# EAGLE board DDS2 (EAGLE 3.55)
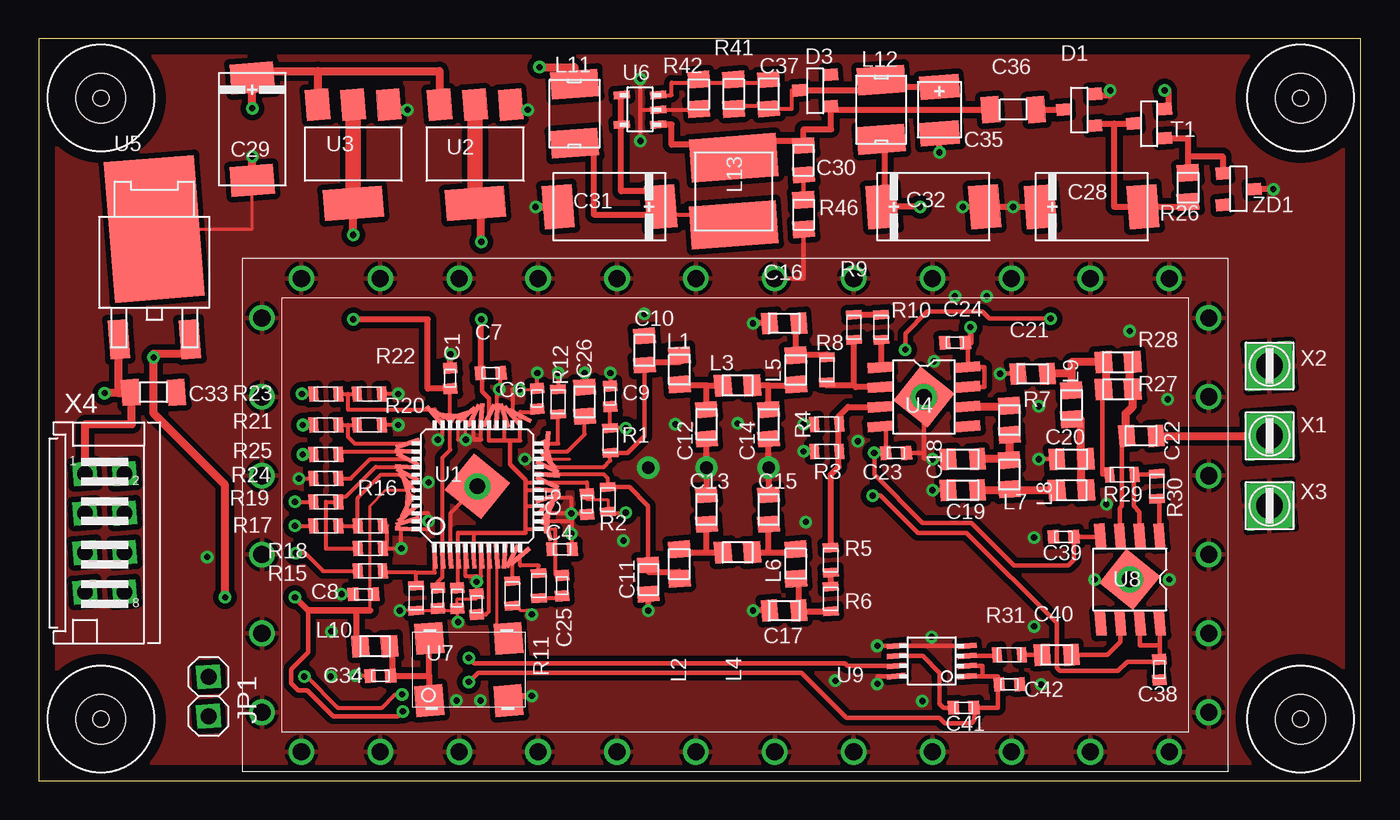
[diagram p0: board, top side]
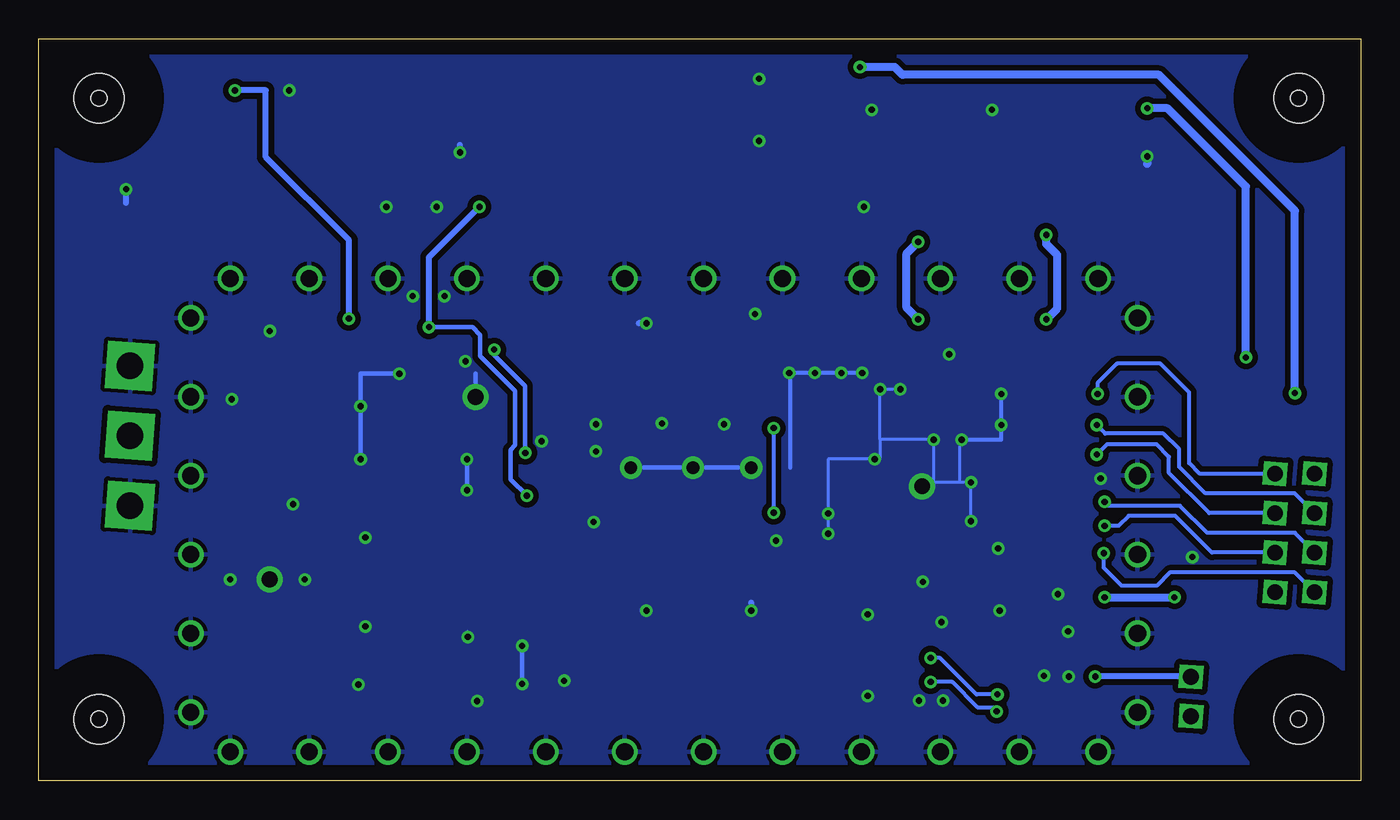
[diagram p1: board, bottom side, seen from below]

Size 85.11 x 47.79 mm. Coordinates in mm from the lower left corner, seen from the top.
Outline: 0,0 85.11,0 85.11,47.79 0,47.79 0,0
Copper layers used: Top, Bottom

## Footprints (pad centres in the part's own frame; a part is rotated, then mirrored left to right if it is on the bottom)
T-0603 = smd 0.7 x 0.9 rotated 4.4:  0.66,0 | smd 0.7 x 0.9 rotated 4.3:  -0.66,0
T-0805 = smd 1.016 x 1.397 rotated 4.4:  0.94,0 | smd 1.016 x 1.397 rotated 4.3:  -0.94,0
J_D = smd 1.93 x 2.794 rotated 4.3:  -3.302,0 | smd 1.93 x 2.794 rotated 4.4:  3.302,0
T-1206 = smd 1.143 x 1.702 rotated 4.4:  1.473,0 | smd 1.143 x 1.702 rotated 4.3:  -1.473,0
J_B = smd 1.524 x 2.54 rotated 4.3:  -1.46,0 | smd 1.524 x 2.54 rotated 4.4:  1.524,0
T-23 = smd 0.787 x 0.889 rotated 4.4:  1.016,1.016 | smd 0.787 x 0.889 rotated 4.3:  -1.016,1.016 | smd 0.787 x 0.889 rotated 4.5:  0,-1.016
02 = drill 1.016 pad 1.524 square:  -1.27,0;  1.27,0
D-0805 = smd 1.092 x 1.397 rotated 4.4:  0.94,0 | smd 1.092 x 1.397 rotated 4.3:  -0.94,0
LE-SMD = smd 1.778 x 3.048 rotated 4.3:  -1.905,0 | smd 1.778 x 3.048 rotated 4.4:  1.905,0
-TPC-M = smd 5.588 x 2.794 rotated 4.3:  0,2.159 | smd 5.588 x 2.794 rotated 4.4:  0,-2.159
D-0603 = smd 0.6 x 1 rotated 4.3:  -0.8,0 | smd 0.6 x 1 rotated 4.4:  0.8,0
31X62 = drill 1.1 pad 1.6 round:  2.54,30.48;  -2.54,30.48;  -12.7,30.48;  12.7,30.48;  -15.24,2.54;  -15.24,7.62;  -15.24,27.94;  15.24,27.94;  15.24,7.62;  15.24,2.54;  15.24,-2.54;  15.24,-27.94;  12.7,-30.48;  2.54,-30.48;  -2.54,-30.48;  -12.7,-30.48;  -15.24,-27.94;  -15.24,-2.54;  15.24,12.7;  -15.24,12.7;  -15.24,-7.62;  15.24,-7.62;  -15.24,22.86;  -15.24,17.78;  15.24,22.86;  15.24,17.78;  -15.24,-12.7;  -15.24,-17.78;  15.24,-12.7;  15.24,-17.78;  15.24,-22.86;  -15.24,-22.86;  -7.62,30.48;  7.62,30.48;  -7.62,-30.48;  7.62,-30.48
T-23' = smd 0.787 x 0.889 rotated 4.3:  0.94,1.016 | smd 0.787 x 0.889 rotated 4.4:  -0.94,1.016 | smd 0.787 x 0.889 rotated 4.5:  0,-1.016
C_SQ48 = smd 1.6 x 0.28 rotated 4.3:  -4.5,2.75;  -4.5,-1.75 | smd 1.6 x 0.28 rotated 4.4:  -4.5,2.25 | smd 1.6 x 0.28 rotated 4.5:  -4.5,1.75;  4.55,-0.25 | smd 1.6 x 0.28 rotated 4.6:  -4.5,1.25 | smd 1.6 x 0.28 rotated 4.7:  -4.5,0.75;  -4.5,0.25 | smd 1.6 x 0.28 rotated 4.8:  -4.5,-0.25 | smd 1.6 x 0.28 rotated 4.9:  -4.5,-0.75 | smd 1.6 x 0.28 rotated 5:  -4.5,-1.25 | smd 1.6 x 0.28 rotated 26.8:  -4.5,-2.25 | smd 1.6 x 0.28 rotated 49.3:  -4.5,-2.75 | smd 0.28 x 1.6 rotated 71.8:  -2.75,-4.5 | smd 0.28 x 1.6 rotated 94.3:  -2.25,-4.5 | smd 0.28 x 1.6 rotated 116.8:  -1.75,-4.5 | smd 0.28 x 1.6 rotated 139.3:  -1.25,-4.5 | smd 0.28 x 1.6 rotated 161.8:  -0.75,-4.5 | smd 0.28 x 1.6 rotated 184.3:  -0.25,-4.5 | smd 0.28 x 1.6 rotated 206.8:  0.25,-4.5 | smd 0.28 x 1.6 rotated 4.4:  0.75,-4.5 | smd 0.28 x 1.6 rotated 26.9:  1.25,-4.5 | smd 0.28 x 1.6 rotated 49.4:  1.75,-4.5 | smd 0.28 x 1.6 rotated 71.9:  2.25,-4.5 | smd 0.28 x 1.6 rotated 94.4:  2.75,-4.5 | smd 1.6 x 0.28 rotated 116.9:  4.55,-2.75 | smd 1.6 x 0.28 rotated 139.4:  4.55,-2.25 | smd 1.6 x 0.28 rotated 161.9:  4.55,-1.75 | smd 1.6 x 0.28 rotated 184.4:  4.55,-1.25 | smd 1.6 x 0.28 rotated 206.9:  4.55,-0.75 | smd 1.6 x 0.28 rotated 27:  4.55,0.25 | smd 1.6 x 0.28 rotated 49.5:  4.55,0.75 | smd 1.6 x 0.28 rotated 72:  4.55,1.25 | smd 1.6 x 0.28 rotated 94.5:  4.55,1.75 | smd 1.6 x 0.28 rotated 117:  4.55,2.25 | smd 1.6 x 0.28 rotated 139.5:  4.55,2.75 | smd 0.28 x 1.6 rotated 162:  2.75,4.5 | smd 0.28 x 1.6 rotated 184.5:  2.25,4.5 | smd 0.28 x 1.6 rotated 207:  1.75,4.5 | smd 0.28 x 1.6 rotated 4.6:  1.25,4.5 | smd 0.28 x 1.6 rotated 27.1:  0.75,4.5 | smd 0.28 x 1.6 rotated 49.6:  0.25,4.5 | smd 0.28 x 1.6 rotated 72.1:  -0.25,4.5 | smd 0.28 x 1.6 rotated 94.6:  -0.75,4.5 | smd 0.28 x 1.6 rotated 117.1:  -1.25,4.5 | smd 0.28 x 1.6 rotated 139.6:  -1.75,4.5 | smd 0.28 x 1.6 rotated 162.1:  -2.25,4.5 | smd 0.28 x 1.6 rotated 184.6:  -2.75,4.5 | smd 3 x 3 rotated 321.2:  0,0
T-223 = smd 1.499 x 2.007 rotated 4.3:  -2.286,-3.175 | smd 1.499 x 2.007 rotated 4.4:  0,-3.175 | smd 1.499 x 2.007 rotated 4.5:  2.286,-3.175 | smd 3.81 x 2.007 rotated 4.6:  0,3.175
-8EXP = smd 0.66 x 1.6 rotated 4.3:  -1.905,-2.819 | smd 0.66 x 1.6 rotated 4.9:  -1.93,2.819 | smd 0.66 x 1.6 rotated 4.4:  -0.635,-2.819 | smd 0.66 x 1.6 rotated 4.5:  0.635,-2.819 | smd 0.66 x 1.6 rotated 4.8:  -0.66,2.819 | smd 0.66 x 1.6 rotated 4.7:  0.61,2.819;  1.88,2.819 | smd 0.66 x 1.6 rotated 4.6:  1.905,-2.819 | smd 2.794 x 2.794 rotated 321.2:  0,0
AK = smd 1.27 x 2.54 rotated 4.3:  -2.286,-2.032 | smd 1.27 x 2.54 rotated 4.4:  2.286,-2.032 | smd 5.8 x 9.1 rotated 4.5:  0,5.08
T23-5 = smd 1.016 x 0.508 rotated 4.3:  -1.143,0.953 | smd 1.016 x 0.508 rotated 4.4:  -1.143,0 | smd 1.016 x 0.508 rotated 4.5:  -1.143,-0.953 | smd 1.016 x 0.508 rotated 4.6:  1.206,-0.953 | smd 1.016 x 0.508 rotated 4.7:  1.206,0.953
710 = smd 1.8 x 2 rotated 4.3:  -2.55,-2 | smd 1.8 x 2 rotated 4.4:  2.55,-2 | smd 1.8 x 2 rotated 4.5:  2.55,2 | smd 1.8 x 2 rotated 4.6:  -2.55,2
SOIC8 = smd 0.356 x 1.219 rotated 4.3:  -0.975,-2.275 | smd 0.356 x 1.219 rotated 4.4:  -0.325,-2.275 | smd 0.356 x 1.219 rotated 4.5:  0.325,-2.275 | smd 0.356 x 1.219 rotated 4.6:  0.975,-2.275 | smd 0.356 x 1.219 rotated 4.7:  0.975,2.275;  0.325,2.275 | smd 0.356 x 1.219 rotated 4.8:  -0.325,2.275 | smd 0.356 x 1.219 rotated 4.9:  -0.975,2.275
IL-3 = hole 3.2: 0,0 | hole 1.016: 0,0
TSEQ = drill 1.702 pad 3.048 square:  0,0
MBG8 = drill 1.016 pad 1.422 square:  -1.27,3.81;  1.27,3.81;  -1.27,1.27;  1.27,1.27;  -1.27,-1.27;  1.27,-1.27;  -1.27,-3.81;  1.27,-3.81

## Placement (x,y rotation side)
C1  100nF  [T-0603]  26.49,25.92 270 top
C2  100nF  [T-0603]  25.69,11.77 90 top
C3  100nF  [T-0603]  26.94,11.77 90 top
C4  100nF  [T-0603]  33.69,14.92 180 top
C5  100nF  [T-0603]  35.29,17.82 90 top
C6  100nF  [T-0603]  32.09,24.62 270 top
C7  100nF  [T-0603]  29.09,26.27 180 top
C8  100nF  [T-0603]  20.89,12.02 0 top
C9  100nF  [T-0603]  36.79,24.77 270 top
C10  2.2pF  [T-0805]  38.99,27.72 270 top
C11  2.2pF  [T-0805]  39.24,12.97 90 top
C12  15pF  [T-0805]  42.99,22.97 90 top
C13  15pF  [T-0805]  42.99,17.47 270 top
C14  18pF  [T-0805]  46.99,22.97 90 top
C15  18pF  [T-0805]  46.99,17.47 270 top
C16  10pF  [T-0805]  47.99,29.47 0 top
C17  10pF  [T-0805]  47.99,10.97 0 top
C18  2.2pF  [T-0805]  59.49,20.72 0 top
C19  15pF  [T-0805]  59.49,18.72 0 top
C20  18pF  [T-0805]  66.49,20.72 0 top
C21  10pF  [T-0805]  63.99,26.22 0 top
C22  100nF  [T-0805]  70.99,22.22 180 top
C23  10nF  [T-0603]  55.19,21.12 180 top
C24  10nF  [T-0603]  58.99,28.22 0 top
C25  100nF  [T-0603]  33.69,12.57 270 top
C26  1uF  [T-0805]  35.14,24.42 90 top
C27  10nF  [T-0603]  28.19,11.37 90 top
C28  TAJ_D  [J_D]  67.79,36.97 0 top
C29  TAJ_D  [J_D]  13.74,41.97 270 top
C30  220pF  [T-0805]  49.24,39.97 90 top
C31  330uF/10 loesr  [J_D]  36.74,36.97 180 top
C32  TAJ_D  [J_D]  57.59,36.97 0 top
C33  220nF  [T-1206]  7.39,25.02 180 top
C34  100nF  [T-0603]  21.99,6.77 0 top
C35  1uF/35  [J_B]  57.99,43.22 270 top
C36  10uF  [T-1206]  62.74,43.22 180 top
C37  220pF  [T-0805]  46.99,44.22 270 top
C38  10nF  [T-0603]  72.14,7.17 90 top
C39  10nF  [T-0603]  65.99,15.72 0 top
C40  100nF  [T-0805]  65.54,8.12 0 top
C41  100nF  [T-0603]  59.54,4.72 0 top
C42  100nF  [T-0603]  62.49,6.22 180 top
D1  BAR-43-S  [T-23]  66.99,43.22 270 top
D3  BAR-43  [T-23]  49.99,44.47 270 top
JP1  PINHD-1X2  [02]  10.93,5.43 270 top
L1  68nH  [D-0805]  41.24,26.47 270 top
L2  68nH  [D-0805]  41.24,13.97 90 top
L3  150nH  [D-0805]  44.99,25.47 0 top
L4  150nH  [D-0805]  44.99,14.72 0 top
L5  150nH  [D-0805]  48.74,26.47 90 top
L6  150nH  [D-0805]  48.74,13.97 270 top
L7  68nH  [D-0805]  62.49,19.72 270 top
L8  150nH  [D-0805]  66.49,18.72 0 top
L9  150nH  [D-0805]  66.49,24.22 90 top
L10  ?  [D-0805]  21.64,8.67 0 top
L11  DALE-SMD 10uH  [LE-SMD]  34.49,42.97 270 top
L12  DALE-SMD 10uH  [LE-SMD]  54.24,43.22 270 top
L13  WE-TPC-M 10uH  [-TPC-M]  44.74,37.97 180 top
R1  91  [D-0603]  36.79,21.92 90 top
R2  91  [D-0603]  36.64,18.12 270 top
R3  160  [D-0603]  50.74,21.22 0 top
R4  160  [D-0603]  50.74,22.97 180 top
R5  20  [D-0603]  50.99,14.22 90 top
R6  20  [D-0603]  50.99,11.72 90 top
R7  47  [D-0805]  62.49,23.22 270 top
R8  200  [D-0603]  50.74,26.47 90 top
R9  200  [D-0603]  52.49,29.22 270 top
R10  200  [D-0603]  54.24,29.22 90 top
R11  1k  [D-0603]  32.19,12.57 90 top
R12  3k9  [D-0603]  33.44,24.42 270 top
R13  10k  [D-0603]  30.49,12.07 270 top
R14  1k8  [D-0603]  24.29,11.77 270 top
R15  1k  [D-0603]  21.34,13.52 0 top
R16  1k8  [D-0603]  21.34,16.42 0 top
R17  1k  [D-0603]  18.49,16.42 0 top
R18  1k8  [D-0603]  21.34,14.97 0 top
R19  1k  [D-0603]  18.49,17.97 0 top
R20  1k8  [D-0603]  21.29,22.92 0 top
R21  1k  [D-0603]  18.49,22.92 0 top
R22  1k8  [D-0603]  21.29,24.92 0 top
R23  1k  [D-0603]  18.49,24.92 0 top
R24  1k  [D-0603]  18.49,19.47 180 top
R25  1k  [D-0603]  18.49,21.02 0 top
R26  ?  [D-0805]  73.99,38.22 90 top
R27  100  [D-0805]  69.49,25.22 180 top
R28  100  [D-0805]  69.49,26.97 180 top
R29  470  [D-0603]  69.74,19.72 180 top
R30  470  [D-0603]  71.99,18.97 90 top
R31  22  [D-0603]  62.49,8.12 180 top
R41  6k8  [D-0805]  44.74,44.22 270 top
R42  1k3  [D-0805]  42.49,44.22 90 top
R46  2k2  [D-0805]  49.24,36.47 90 top
S1  S31-62  [31X62]  44.84,17.11 90 top
T1  BC807-40  [T-23']  71.49,42.34 270 top
U1  AD9951  [C_SQ48]  28.24,18.97 90 top
U2  REG1117A  [T-223]  28.09,40.37 180 top
U3  REG1117A  [T-223]  20.24,40.37 180 top
U4  AD8000  [-8EXP]  56.99,24.72 270 top
U5  LF-33  [AK]  7.44,30.47 0 top
U6  TPS61041  [T23-5]  38.74,43.22 180 top
U7  SG-710  [710]  27.69,7.17 0 top
U8  AD8000  [-8EXP]  70.24,12.97 180 top
U9  AD8361  [SOIC8]  57.49,7.72 90 top
U$30  [IL-3]  81.24,43.97 0 top
U$31  [IL-3]  81.24,3.97 0 top
U$53  [IL-3]  3.99,3.97 0 top
U$54  [IL-3]  3.99,43.97 0 top
X1  HF  [TSEQ]  79.24,22.22 0 top
X2  -  [TSEQ]  79.24,26.72 0 top
X3  -  [TSEQ]  79.24,17.72 0 top
X4  LUMBG8  [MBG8]  4.24,15.97 0 top
ZD1  BZX84C3.3  [T-23]  77.24,38.1 90 top

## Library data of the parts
C1-C27 C30 C33 C34 C36-C42 = C_KERAM
C28 C29 C31 C32 C35 = ELKO_LG
D1 D3 ZD1 = DIODEN
JP1 = PINHD-Q
L1-L13 = L
R1-R31 R41 R42 R46 = R
S1 = Shields
T1 = TR_PNP
U1 U4 U8 U9 = ANALOG_D
U2 U3 U6 = TI
U5 = SGS
U7 = SEIK_EPS
U$30 U$31 U$53 U$54 = Z_SPECIA
X1-X4 = Z_CONNEC

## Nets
+3,3V: C8. C29. C41. C42. L10. U1. U2. U3. U5. U9.
+6VOLT: C33. L11. U5. X4.
+8VOLT: C24. C32. C38. L12. U4. U8.
+IOUT: C10. L1. R1. U1.
-3VOLT: C23. C39. T1. U4. U8.
-IOUT: C11. L2. R2. U1.
AVDD: C3. C4. C5. C6. C7. C9. C25. R1. R2. U1. U2.
BHO: C21. L9. R27. R28. R29.
DIFF: C40. U8.
DVDD: C1. C2. U1. U3.
GND: C1. C2. C3. C4. C5. C6. C7. C8. C9. C10. C11. C12. C13. C14. C15. C16. C17. C18. C19. C20. C21. C23. C24. C26. C27. C28. C29. C31. C32. C33. C34. C35. C38. C39. C42. D1. JP1. R3. R4. R12. R13. R14. R16. R18. R20. R22. R24. R42. R46. S1. U1. U2. U3. U4. U5. U6. U7. U8. U9. X2. X3. X4. ZD1.
HFO: C22. R27. R28. U8.
IOSYNC: R21. X4.
IOUPD: R15. X4.
N$1: R10. U4.
N$2: C12. L1. L3.
N$3: R8. R9. U4.
N$4: C14. L3. L5.
N$5: C40. R31.
N$6: C16. L5. R8.
N$7: C18. L7. R7.
N$8: C13. L2. L4.
N$9: C15. L4. L6.
N$10: C17. L6. R6.
N$11: R5. R6.
N$12: R7. U4.
N$13: R9. R10.
N$14: R13. U1.
N$15: C19. L7. L8.
N$16: C20. L8. L9.
N$17: C22. X1.
N$18: R3. R4. R5. U4.
N$19: C34. L10. U7.
N$20: C27. U1.
N$21: R14. R15. U1.
N$22: C37. R41. R42. U6.
N$23: C30. C36. D3. L13. U6.
N$24: C25. R11.
N$25: R11. U1.
N$26: R25. U1.
N$27: R12. U1.
N$28: C35. C37. D3. L12. R41.
N$29: C26. U1.
N$30: C31. L11. L13. U6.
N$31: R16. R17. U1.
N$32: C30. R46.
N$33: R18. R19. U1.
N$34: R24. U1.
N$35: R20. R21. U1.
N$36: R22. R23. U1.
N$37: C28. D1. R26. T1.
N$38: C36. D1.
N$39: R29. R30. U8.
N$40: R26. T1. ZD1.
N$41: R30. U8.
N$42: R31. U9.
N$44: C41. U9.
REF_CLK: U1. U7.
RESET: R23. X4.
SCLK: R19. X4.
SDIO: R17. X4.
SDO: R25. X4.
VRMS: JP1. U9.

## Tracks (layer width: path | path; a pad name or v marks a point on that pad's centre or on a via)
+3,3V  (via drill 0.4 pad 0.8)
  Top 0.2: 23.74,18.72 22.34,18.72 21.34,17.72 21.34,12.07 | 21.34,12.07 21.34,12.02 21.55,12.02 | 21.34,10.97 21.34,12.07
  Top 0.3: 60.74,6.75 59.77,6.75 | 59.77,7.39 60.74,7.39 60.74,6.75 | 61.74,6.22 61.83,6.22 | 60.74,6.75 61.74,6.75 61.74,6.22 | 60.24,4.72 60.2,4.72 | 60.24,4.72 61.74,4.72 61.74,6.22 | 20.44,8.67 L10. | v23.44,4.47 23.14,4.17 18.94,4.17 17.29,5.82 16.69,5.82 16.24,6.27 16.24,7.17 17.34,8.27 17.34,10.97 | v27.69,6.37 28.29,6.97 49.09,6.97 51.99,4.07 57.99,4.07 58.34,3.72 60.04,3.72 60.24,3.92 60.24,4.72
  Top 0.4: L10. | 20.44,10.97 20.44,8.67
  Top 0.406: v16.49,11.82 17.34,10.97 20.44,10.97 21.34,10.97
  Top 0.5: 17.95,45.72 17.95,43.55 | 17.95,45.72 13.74,45.72 13.74,45.27 v13.74,43.32 | 25.8,43.55 25.8,45.72 17.95,45.72 | v11.99,11.82 11.99,19.07 7.39,23.67 7.39,27.52 | 9.73,28.44 9.74,28.44 9.74,27.52 7.39,27.52 | 7.39,27.52 v7.39,27.27
  Bottom 0.25: v27.69,6.37 26.29,6.37 24.64,4.72 23.69,4.72 v23.44,4.47
  Bottom 0.5: v16.49,11.82 v11.99,11.82 | v13.74,43.32 12.44,43.32 7.39,38.27 v7.39,27.27
+6VOLT  (via drill 0.4 pad 0.8)
  Top 0.5: 2.99,19.78 2.99,19.72 | 2.97,19.78 2.99,19.78 | 2.99,19.78 2.99,22.97 5.99,22.97 5.99,25.02 5.92,25.02 5.92,24.97 5.24,24.97 | 5.15,28.44 5.15,24.97 5.24,24.97 | v32.24,45.97 34.49,45.97 34.49,44.88 | 5.24,24.97 v4.24,24.97
  Bottom 0.5: v32.24,45.97 29.99,45.97 29.49,45.47 12.99,45.47 4.24,36.72 v4.24,24.97
+8VOLT  (via drill 0.4 pad 0.8)
  Top 0.3: 59.81,25.38 60.89,25.38 60.89,26.65 59.81,26.65 59.81,28.22 59.65,28.22 59.64,28.22 | v53.69,18.37 54.19,18.37 56.59,15.97 59.74,15.97 65.54,10.17 65.54,7.27 65.74,7.07 69.49,7.07 70.09,7.67 72.14,7.67 72.14,7.77 | 72.14,7.77 72.14,7.83 | 72.17,8.72 72.17,7.77 72.14,7.77 | 70.9,10.15 70.9,8.72 72.17,8.72 | 72.17,8.72 72.17,10.15
  Top 0.4: L12. 54.49,41.31 54.49,36.97 54.29,36.97 v56.74,36.97 | 59.65,28.22 59.99,28.22 v59.99,29.22
  Bottom 0.3: v59.99,29.22 57.19,29.22 56.69,28.72 56.69,27.37 54.44,25.12 54.44,21.62 54.74,21.32 54.74,19.42 v53.69,18.37
  Bottom 0.4: v56.74,36.97 59.99,33.72 v59.99,29.22
+IOUT
  Top 0.25: 36.79,21.12 36.79,20.62 36.39,20.22 32.74,20.22
  Top 0.3: 36.79,21.12 37.89,21.12 38.99,22.22 38.99,26.78
  Top 0.4: 38.99,26.78 38.99,26.97 41.24,26.97 L1.
-3VOLT  (via drill 0.4 pad 0.8)
  Top 0.3: 54.17,22.81 54.54,22.81 54.54,21.12 54.53,21.12 v53.79,21.12 53.79,19.72 56.89,16.62 60.04,16.62 62.79,13.87 66.29,13.87 66.65,14.23 66.65,15.72 | v55.79,27.77 55.79,28.82 57.19,30.22 60.74,30.22 61.19,29.77 v65.14,29.77 | 66.65,15.72 66.64,15.72 | 68.33,15.79 68.33,15.72 66.65,15.72
  Top 0.4: v72.49,44.47 72.74,44.47 72.74,43.22 72.51,43.22 72.51,43.27
  Bottom 0.3: v53.79,21.12 53.79,25.42 55.79,27.42 v55.79,27.77
  Bottom 0.4: v65.14,29.77 65.14,34.82 70.49,40.17 70.49,44.47 v72.49,44.47
-IOUT
  Top 0.25: 32.74,19.72 36.39,19.72 36.64,19.47 36.64,18.92
  Top 0.3: 36.64,18.92 38.04,18.92 39.24,17.72 39.24,13.91
  Top 0.4: L2. 41.24,13.47 39.24,13.47 39.24,13.91
AVDD  (via drill 0.4 pad 0.8)
  Top 0.2: 31.34,16.22 31.94,16.22 | 31.94,16.22 32.74,16.22 33.24,16.22 | 31.94,16.22 31.94,16.27 | 33.24,14.92 33.03,14.92 | 35.29,18.48 35.29,18.12 36.64,18.12 R2. 36.64,17.42
  Top 0.25: 26.99,15.97 26.99,14.47 26.99,12.43 26.94,12.43 | 27.99,15.97 27.99,14.47 | 31.34,16.22 32.74,16.22 | 31.34,17.72 32.74,17.72 | 31.34,18.72 32.74,18.72 | 31.34,19.22 32.74,19.22 35.29,19.22 35.29,18.48 | 30.99,21.92 30.99,23.52 30.99,23.77 32.09,23.77 32.09,23.96 | 29.99,21.92 29.99,23.52 | 28.99,21.92 28.99,23.52 | 33.24,16.22 33.24,14.92 33.24,13.32 33.69,13.32 C25. | 36.79,24.11 R1. v37.79,22.72 | R2. 36.64,17.27 v37.79,17.27
  Top 0.3: 26.99,15.97 27.99,15.97 31.34,15.97 31.34,16.22 31.34,17.72 31.34,18.72 31.34,19.22 31.34,19.37 30.34,20.37 30.34,21.92 | 30.34,21.92 30.99,21.92 | 30.34,21.92 29.99,21.92 28.99,21.92 | 28.99,23.52 28.99,24.62 28.54,25.07 28.54,26.27 28.43,26.27
  Top 0.4: 28.43,26.27 28.49,26.27 v28.49,29.72
  Top 0.5: U2. 28.49,37.2 v28.49,34.72
  Top 1: U2. 28.09,43.55
  Bottom 0.25: v37.79,17.27 v37.79,22.72
  Bottom 0.5: v28.49,29.72 29.24,30.47 29.24,33.97 v28.49,34.72
BHO
  Top 0.3: 66.49,25.42 66.49,25.16 | R29. 68.49,19.72 68.49,24.97 68.74,25.22
  Top 0.5: 66.49,26.22 64.93,26.22 | 66.49,26.22 66.49,25.42 | 66.49,26.22 66.49,26.97 68.55,26.97 68.74,26.97 68.74,25.22 68.55,25.22
DIFF
  Top 0.3: 69.63,10.15 69.63,8.96 68.79,8.12 66.48,8.12
DVDD  (via drill 0.4 pad 0.8)
  Top 0.25: 26.49,25.26 26.49,23.52 26.49,21.32 25.99,20.82 25.99,14.47 25.99,13.12 25.69,12.82 25.69,12.43
  Top 0.4: 26.49,25.26 25.04,25.26 25.04,29.72 v20.24,29.72
  Top 0.5: v20.24,35.17 U3.
  Top 1: U3. 20.24,43.55
  Bottom 0.5: v20.24,29.72 19.54,30.42 19.54,33.87 20.24,34.57 v20.24,35.17
GND  (via drill 0.4 pad 0.8, 0.81 pad 1.42, 1.02 pad 1.68)
  Top 0.2: 26.99,21.97 26.99,23.52 | v27.49,21.97 27.49,23.52 | 30.49,25.22 v30.94,25.22 32.09,25.22 C6. | 34.29,14.92 C4. | 35.29,17.22 C5. | 32.74,20.72 34.19,20.72 | v19.49,12.02 C8. | U5. 13.74,35.55 C29. | R13. 30.69,11.27 30.99,10.97 31.49,10.97 v31.74,10.72 | R14. 24.24,10.97 | 24.24,10.97 v23.24,10.97 | C3. 26.94,10.27 v26.99,10.22 | C3. 26.94,10.97 25.69,10.97 | 25.69,10.97 C2. | 24.24,10.97 25.69,10.97 | C3. 26.94,11.72 28.19,11.72 28.19,12.03 v28.19,12.82 28.19,13.17
  Top 0.25: 25.99,23.52 25.99,22.27 v25.69,21.97 | v25.09,19.22 23.74,19.22 | 27.99,23.52 27.99,21.97 v27.49,21.97 | v25.09,16.72 25.09,16.22 23.74,16.22 23.34,16.22 v23.34,14.97 22.44,14.97 | v25.09,16.72 23.74,16.72 | 23.74,17.22 25.09,17.22 v25.09,16.72 | 30.49,25.22 30.49,23.52 | 29.49,23.52 29.49,25.07 v29.64,25.22 29.74,25.32 C7. | 28.49,21.97 28.49,23.52 | 34.29,16.72 v34.29,15.92 34.29,14.92 | 34.29,16.72 32.74,16.72 | v34.29,17.22 34.29,16.72 | v34.29,17.22 32.74,17.22 | v34.29,17.22 34.29,18.22 32.74,18.22 | v34.29,17.22 35.29,17.22 | v31.29,20.72 32.74,20.72 | v36.79,26.27 C9. | v35.14,26.27 35.14,25.36 | C6. v32.09,26.27 | v33.44,26.27 33.44,25.22 | 26.49,14.47 26.49,17.22 U1. | C34. v20.39,6.77 | R18. 22.44,14.97 | R16. 22.44,16.42 22.44,14.97 | v23.14,22.92 R20. | v23.14,24.92 R22. | v16.74,19.47 R24. | 28.49,14.47 28.49,13.17 28.19,13.17 27.49,13.17 27.49,14.47 | 38.74,43.22 39.88,43.22 42.49,43.22 R42. | 38.74,43.22 v38.74,45.22 | v38.74,41.22 38.74,43.22
  Top 0.3: v27.49,21.97 26.99,21.97 | 27.99,21.97 28.49,21.97 | v61.89,26.22 C21. | 56.99,24.67 U4. 56.99,21.12 | v64.39,20.72 C20. | v57.54,18.72 C19. | C18. v57.54,20.72 57.54,20.77 56.99,20.77 56.99,21.12 | 56.99,21.12 C23. | 47.39,32.35 49.24,32.35 R46. | 57.49,8.7 59.77,8.7 | 57.49,8.7 55.22,8.7 v53.99,8.7 | 57.49,8.7 v57.49,9.27 | v53.99,6.25 53.99,6.75 U9.
  Top 0.4: C14. v46.99,20.17 C15. | C12. v42.99,20.17 C13. | 30.24,5.17 30.24,5.47 v31.74,5.47 | C17. v45.99,10.97 | C11. v39.24,10.97 | C16. v45.99,29.47 | 49.94,21.22 v49.24,21.22 | R4. v49.24,22.97 | C1. v26.49,27.47 | v57.99,40.47 C35. | v59.49,36.97 C32. v62.74,36.97 64.49,36.97 | 68.01,44.16 68.99,44.16 v68.99,44.47 | v79.49,38.1 ZD1.
  Top 0.5: C29. v13.74,40.22 | 22.53,43.55 22.53,43.22 v23.74,43.22 | 30.38,43.55 30.38,43.22 v31.49,43.22 | v31.99,36.97 C31.
  Bottom 0.2: 25.79,19.22 v25.09,19.22 v25.09,16.72 | 27.49,18.97 U1. | 27.49,18.97 27.49,19.22 25.79,19.22 | 25.79,19.22 25.79,21.97 v25.69,21.97 | 27.49,18.97 v27.49,21.97 30.94,21.97 | 30.94,24.92 v30.94,25.22 v29.64,25.22 | 30.94,21.97 30.94,24.87 | v34.29,15.92 v34.29,17.22 34.29,20.72 v31.29,20.72 30.94,20.72 30.94,21.97 | v19.49,12.02 19.74,12.02 | v31.74,10.72 31.74,10.47 | v23.24,10.97 23.49,10.97 | v26.99,10.22 26.99,9.97
  Bottom 0.25: 36.74,26.27 36.74,25.47 | 36.74,26.27 36.74,20.17 | 36.74,26.27 v35.14,26.27 v33.44,26.27 v32.09,26.27 | 36.74,26.27 v36.79,26.27 | v23.34,14.97 23.59,14.97 | v25.69,21.97 23.14,21.97 v23.14,22.92 v23.14,24.92 | v38.74,41.22 38.74,40.97
  Bottom 0.3: v46.99,20.17 v42.99,20.17 v39.24,20.17 | U4. 56.99,26.22 | 64.39,20.67 v64.39,20.72 64.39,26.22 v61.89,26.22 | v57.54,18.72 v57.54,20.72 | v57.49,9.27 57.49,9.57 | v53.99,6.25 v53.99,8.7
  Bottom 0.4: v31.74,5.47 31.49,5.47 | v45.99,10.97 46.24,10.97 | v39.24,10.97 39.24,11.47 | v45.99,29.47 46.49,29.47 | v49.24,21.22 49.49,21.22 | v49.24,22.97 49.49,22.97 | v26.49,27.47 26.49,27.72 | v57.99,40.47 57.99,40.97 | v59.49,36.97 59.74,36.97 | v68.99,44.47 68.99,44.72 | v62.74,36.97 62.99,36.97 | 79.49,37.22 v79.49,38.1
  Bottom 0.5: v13.74,40.22 13.74,39.72
  other vias: 28.24,18.97 56.99,24.72 18.84,9.62 37.64,15.47 44.99,23.02 40.99,22.97 38.99,30.07 49.39,16.67 52.74,21.87 10.84,14.42 64.39,24.12 70.24,28.97 72.69,24.57 68.74,17.82 64.09,15.67 72.79,12.97 67.99,12.97 70.24,12.97 51.29,6.44 56.89,5.14 64.09,9.95 64.54,6.19 18.79,6.72 28.44,5.17 26.89,5.17 57.64,27.02 61.04,31.22 58.99,31.22
  pour Bottom (isolate 0.356): 0.74,47.26 0.74,0.47 84.74,0.47 84.74,47.26
  pour Top (isolate 0.356): 0.74,47.26 0.74,0.47 84.74,0.47 84.74,47.26
HFO
  Top 0.3: 69.99,22.22 69.74,21.97 69.74,17.72 69.6,17.58 69.6,15.79
  Top 0.5: R28. 70.24,26.97 70.24,25.22 R27. 70.43,24.11 69.99,23.67 69.99,22.22 70.05,22.22
IOSYNC  (via drill 0.4 pad 0.8)
  Top 0.25: v16.99,22.92 17.69,22.92
  Bottom 0.25: 2.97,17.24 4.25,18.52 9.99,18.52 11.69,20.22 11.69,21.37 12.69,22.37 16.44,22.37 v16.99,22.92
IOUPD  (via drill 0.4 pad 0.8)
  Top 0.25: 20.54,13.52 18.29,13.52 17.14,14.67 v16.54,14.67
  Bottom 0.25: 2.97,12.16 4.23,13.42 12.29,13.42 13.14,12.57 15.39,12.57 16.54,13.72 v16.54,14.67
N$1
  Top 0.4: 54.24,28.47 54.24,28.42 54.24,26.62 54.17,26.62
N$2
  Top 0.4: 42.99,23.91 42.99,25.47 | 42.99,25.47 L3. | 41.24,25.53 41.24,25.47 42.99,25.47
N$3
  Top 0.4: 52.49,25.47 R9. | 54.17,25.36 52.61,25.36 52.49,25.47 | 50.74,25.67 50.74,25.47 52.49,25.47
N$4
  Top 0.4: 46.99,23.91 46.99,25.47 | 46.99,25.47 45.93,25.47 | L5. 48.74,25.47 46.99,25.47
N$5
  Top 0.3: 63.29,8.12 C40.
N$6
  Top 0.4: R8. 50.74,27.47 48.74,27.47 | 48.74,27.41 48.74,27.47 | 48.93,29.47 48.74,29.47 48.74,27.47
N$7
  Top 0.3: 62.44,20.72 62.44,20.66 L7.
  Top 0.5: 62.49,22.28 L7. | 62.44,20.72 60.43,20.72
N$8
  Top 0.4: 42.99,14.72 L4. | 42.99,14.72 42.99,16.53 | 41.24,14.91 41.24,14.72 42.99,14.72
N$9
  Top 0.4: 46.99,14.72 46.99,16.53 | 45.93,14.72 46.99,14.72 | L6. 48.74,14.72 46.99,14.72
N$10
  Top 0.4: 50.99,10.92 49.04,10.92 48.99,10.97 48.93,10.97 48.93,12.78 48.74,12.97 48.74,13.03
N$11
  Top 0.4: 50.99,12.47 R6. 50.99,13.42
N$12
  Top 0.3: 62.49,24.11 R7.
  Top 0.5: R7. | 59.81,24.11 62.49,24.11
N$13
  Top 0.4: R10. 54.24,29.97 54.19,30.02 52.49,30.02
N$14
  Top 0.25: 30.49,12.87 30.49,14.47
N$15
  Top 0.3: 62.49,18.78 62.49,18.82 | 62.49,18.78 62.49,18.72 | 62.49,18.78 62.44,18.78 62.44,18.72
  Top 0.5: 62.49,18.72 L8. | 60.43,18.72 62.44,18.72
N$16
  Top 0.3: 67.09,20.72 67.43,20.72 67.14,20.72 | 67.43,18.72 67.14,18.72
  Top 0.5: L9. 67.09,23.28 67.09,20.72 | 67.14,18.72 67.14,20.72
N$17
  Top 0.5: C22. X1.
N$18
  Top 0.4: R5. 50.99,19.72 51.49,20.22 51.49,21.22 | 51.49,21.22 R3. | 51.49,21.22 51.49,22.97 51.54,22.97 51.54,23.42 51.49,23.47 52.11,24.08 54.17,24.08
N$19
  Top 0.25: 22.65,6.77 22.79,6.77 | 22.79,8.67 22.58,8.67
  Top 0.4: 25.14,6.77 22.79,6.77 22.79,8.67 | 25.14,6.77 U7. | 25.14,6.77 25.14,5.17
N$20
  Top 0.25: C27. 28.78,10.71 28.99,10.92 28.99,14.47
N$21
  Top 0.25: 25.49,14.47 25.49,13.42 24.29,13.42 | 24.29,12.57 24.29,13.42 | R15. 22.14,13.42 24.29,13.42
N$22
  Top 0.25: 39.88,44.17 40.74,44.17 40.74,44.97 42.49,44.97 | 42.49,44.97 42.49,45.16 | 42.49,44.97 44.74,44.97 | C37. 46.99,44.97 44.74,44.97 | 44.74,44.97 R41.
N$23
  Top 0.25: 44.74,40.97 L13. 44.74,41.22 | 49.24,41.22 49.24,40.91
  Top 0.4: 39.88,42.27 40.74,42.27 40.74,40.97 44.74,40.97 | 44.74,41.22 49.24,41.22 49.24,41.97 51.01,41.97 51.01,43.45 51.01,43.22 61.27,43.22
N$24
  Top 0.25: 33.69,11.91 33.69,11.77 32.19,11.77
N$25
  Top 0.25: R11. 32.19,13.87 30.99,13.87 30.99,14.47
N$26
  Top 0.25: 23.74,21.22 19.29,21.22 R25.
N$27
  Top 0.25: 32.74,21.72 33.44,21.72 R12.
N$28
  Top 0.25: 44.74,43.28 44.74,43.47 46.99,43.47 46.99,43.28 48.49,43.28 48.49,44.47 D3.
  Top 0.4: 57.99,44.68 57.99,44.72 54.24,44.72 | 54.24,44.72 54.24,45.12 | 54.24,44.72 54.24,44.47 D3.
N$29
  Top 0.25: 32.74,21.22 34.04,21.22 35.14,22.32 C26.
N$30
  Top 0.25: 37.49,42.27 U6. | 37.49,44.17 37.53,44.17 | 35.74,41.06 L11. | 40.04,36.97 39.74,36.97 39.74,36.72 | 39.74,36.72 39.74,36.47 44.74,36.47 44.74,35.81 | 39.74,36.72 39.74,37.97
  Top 0.4: 37.49,44.17 37.49,42.27 37.49,37.97 39.74,37.97 | 35.74,41.06 35.74,36.47 39.74,36.47
N$31
  Top 0.25: 23.74,19.72 22.04,19.72 20.54,18.22 20.54,16.42 R17.
N$32
  Top 0.3: 49.24,37.41 C30.
N$33
  Top 0.25: 20.54,14.97 18.49,14.97 18.49,17.97 R19. 19.29,18.32 19.79,18.32 21.69,20.22 23.74,20.22
N$34
  Top 0.25: 23.74,20.72 21.34,20.72 20.09,19.47 19.29,19.47
N$35
  Top 0.25: 23.74,21.72 20.34,21.72 19.89,22.17 19.89,22.92 | 19.89,22.92 20.49,22.92 | R21. 19.89,22.92
N$36
  Top 0.25: 25.49,23.52 25.49,23.92 19.89,23.92 19.89,24.92 | 19.89,24.92 20.49,24.92 | R23. 19.89,24.92
N$37
  Top 0.4: T1. 69.24,42.34 69.24,41.97 | 69.24,41.97 69.24,36.97 C28. 73.99,36.97 R26. | 68.01,42.28 69.24,42.28 69.24,41.97
N$38
  Top 0.4: C36. D1.
N$39
  Top 0.3: 70.88,15.79 70.88,17.33 70.49,17.72 70.49,19.72 70.54,19.72 71.99,19.72 R30.
N$40
  Top 0.4: 72.51,41.39 73.99,41.39 73.99,40.22 | 73.99,40.22 73.99,39.16 | 76.22,39.05 76.22,40.22 73.99,40.22
N$41
  Top 0.3: 71.99,18.17 71.99,18.22 72.14,18.22 72.14,15.79
N$42
  Top 0.3: 59.77,8.04 61.69,8.04 R31.
N$44
  Top 0.3: 55.22,8.04 56.91,8.04 57.99,6.97 57.99,4.97 58.24,4.72 C41.
REF_CLK
  Top 0.2: 30.24,8.92 30.24,9.22 29.49,9.97 29.49,14.47
  Top 0.25: 30.24,8.92 30.24,9.17
RESET  (via drill 0.4 pad 0.8)
  Top 0.25: v16.94,24.92 17.69,24.92
  Bottom 0.25: 5.51,19.78 10.35,19.78 11.04,20.47 11.04,25.02 12.89,26.87 15.69,26.87 16.94,25.62 v16.94,24.92
SCLK  (via drill 0.4 pad 0.8)
  Top 0.25: v16.49,17.97 17.69,17.97
  Bottom 0.25: 2.97,14.7 4.24,15.97 9.89,15.97 11.64,17.72 16.24,17.72 v16.49,17.97
SDIO  (via drill 0.4 pad 0.8)
  Top 0.25: v16.49,16.42 17.69,16.42
  Bottom 0.25: 5.51,14.7 9.57,14.7 11.94,17.07 14.94,17.07 15.59,16.42 v16.49,16.42
SDO  (via drill 0.4 pad 0.8)
  Top 0.25: 17.69,21.02 17.59,21.02 17.54,20.97 17.49,21.02 v16.99,21.02
  Bottom 0.25: 5.51,17.24 9.76,17.24 12.34,19.82 12.34,20.87 13.14,21.67 16.34,21.67 v16.99,21.02
VRMS  (via drill 0.4 pad 0.8)
  Top 0.25: v17.09,6.72 17.24,6.72 19.24,4.72 22.09,4.72 22.94,5.57 v23.39,5.57
  Top 0.3: v27.69,7.92 28.04,7.57 51.89,7.57 52.07,7.39 55.22,7.39
  Bottom 0.25: v23.39,5.57 24.74,5.57 27.09,7.92 v27.69,7.92
  Bottom 0.4: 10.93,6.7 10.93,6.72 v17.09,6.72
